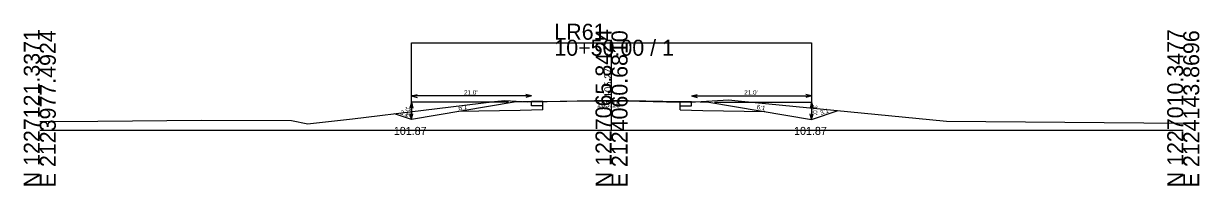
# Model space of a CAD drawing. Extents: x 2126751 to 2128979, y 1225108 to 1234639.
# Drawn here: x 2127773.8 to 2127979.4, y 1225607.5 to 1225635.9 of the extents above; entities that cross this region are included whole.
import ezdxf

# ---------------------------------------------------------------- set-up
doc = ezdxf.new("R2010")
doc.units = 0
for name, color, linetype in [('XS_CELL', 7, 'Continuous'), ('XS_M_DITCH', 7, 'Continuous'), ('XS_P_FINISHED_GRADE', 7, 'Continuous'), ('XS_P_FINISHED_GRADE_ELEV_TX', 7, 'Continuous'), ('XS_P_SUBGRADE_GRANULAR', 7, 'Continuous'), ('XS_P_SUBGRADE_LEVELING', 7, 'Continuous'), ('XS_P_SUBGRADE_PAVEMENT', 7, 'Continuous'), ('XS_P_TX_CLEARZONE', 7, 'Continuous'), ('XS_P_TX_DCH', 7, 'Continuous'), ('XS_P_TX_FS_BS', 7, 'Continuous'), ('XS_X_GROUND', 7, 'Continuous'), ('XS_X_GROUND_TX', 7, 'Continuous')]:
    doc.layers.add(name, color=color, linetype=linetype)

msp = doc.modelspace()

# ---------------------------------------------------------------- linework, layer by layer
at = {"layer": 'XS_CELL'}
for p, q in [((2127876.61, 1225617.21), (2127876.61, 1225633.04)), ((2127776.61, 1225617.21), (2127876.61, 1225617.21)), ((2127876.61, 1225617.21), (2127976.61, 1225617.21))]:
    msp.add_line(p, q, dxfattribs=at)
at = {"layer": 'XS_M_DITCH'}
for p, q in [((2127841.61, 1225619.08), (2127841.61, 1225632.48)), ((2127841.61, 1225632.48), (2127911.61, 1225632.48)), ((2127911.61, 1225632.48), (2127911.61, 1225619.08))]:
    msp.add_line(p, q, dxfattribs=at)
at = {"layer": 'XS_P_FINISHED_GRADE'}
for p, q in [((2127859.61, 1225622.08), (2127841.61, 1225619.08)), ((2127862.61, 1225622.2), (2127859.61, 1225622.08)), ((2127864.61, 1225622.24), (2127862.61, 1225622.2)), ((2127864.61, 1225622.24), (2127876.61, 1225622.48)), ((2127876.61, 1225622.48), (2127888.61, 1225622.24)), ((2127888.61, 1225622.24), (2127890.61, 1225622.2)), ((2127890.61, 1225622.2), (2127893.61, 1225622.08)), ((2127893.61, 1225622.08), (2127911.61, 1225619.08)), ((2127841.61, 1225619.08), (2127838.66, 1225620.07)), ((2127911.61, 1225619.08), (2127916.26, 1225620.63))]:
    msp.add_line(p, q, dxfattribs=at)
at = {"layer": 'XS_P_SUBGRADE_GRANULAR'}
for p, q in [((2127864.61, 1225620.74), (2127864.61, 1225621.49)), ((2127888.61, 1225620.74), (2127888.61, 1225621.49)), ((2127860.61, 1225620.66), (2127849.79, 1225620.45)), ((2127862.61, 1225620.7), (2127860.61, 1225620.66)), ((2127864.61, 1225620.74), (2127862.61, 1225620.7)), ((2127888.61, 1225620.74), (2127890.61, 1225620.7)), ((2127890.61, 1225620.7), (2127892.61, 1225620.66)), ((2127892.61, 1225620.66), (2127903.43, 1225620.45))]:
    msp.add_line(p, q, dxfattribs=at)
at = {"layer": 'XS_P_SUBGRADE_LEVELING'}
for p, q in [((2127864.61, 1225622.2), (2127868.79, 1225622.27)), ((2127864.61, 1225622.24), (2127864.61, 1225622.2)), ((2127868.79, 1225622.27), (2127876.28, 1225622.36)), ((2127876.28, 1225622.36), (2127876.61, 1225622.36)), ((2127876.61, 1225622.36), (2127881.51, 1225622.27)), ((2127881.51, 1225622.27), (2127888.61, 1225622.13)), ((2127888.61, 1225622.24), (2127888.61, 1225622.13))]:
    msp.add_line(p, q, dxfattribs=at)
at = {"layer": 'XS_P_SUBGRADE_PAVEMENT'}
for p, q in [((2127862.61, 1225621.45), (2127862.61, 1225622.2)), ((2127864.61, 1225621.49), (2127862.61, 1225621.45)), ((2127864.61, 1225621.49), (2127864.61, 1225622.2)), ((2127888.61, 1225621.49), (2127888.61, 1225622.13)), ((2127888.61, 1225621.49), (2127890.61, 1225621.45)), ((2127890.61, 1225621.45), (2127890.61, 1225622.2))]:
    msp.add_line(p, q, dxfattribs=at)
at = {"layer": 'XS_P_TX_CLEARZONE'}
for p, q in [((2127841.61, 1225623.2), (2127842.61, 1225623.45)), ((2127841.61, 1225623.2), (2127842.61, 1225622.95)), ((2127862.61, 1225623.2), (2127841.61, 1225623.2)), ((2127862.61, 1225623.2), (2127861.61, 1225623.45)), ((2127862.61, 1225623.2), (2127861.61, 1225622.95)), ((2127890.61, 1225623.2), (2127891.61, 1225623.45)), ((2127890.61, 1225623.2), (2127891.61, 1225622.95)), ((2127890.61, 1225623.2), (2127911.61, 1225623.2)), ((2127911.61, 1225623.2), (2127910.61, 1225623.45)), ((2127911.61, 1225623.2), (2127910.61, 1225622.95)), ((2127841.61, 1225622.08), (2127841.36, 1225621.08)), ((2127841.61, 1225622.08), (2127841.86, 1225621.08)), ((2127841.61, 1225622.08), (2127841.61, 1225619.08)), ((2127858.61, 1225622.08), (2127841.61, 1225622.08)), ((2127894.61, 1225622.08), (2127911.61, 1225622.08)), ((2127911.61, 1225622.08), (2127911.36, 1225621.08)), ((2127911.61, 1225622.08), (2127911.61, 1225619.08)), ((2127911.61, 1225622.08), (2127911.86, 1225621.08)), ((2127841.61, 1225619.08), (2127841.36, 1225620.08)), ((2127841.61, 1225619.08), (2127841.86, 1225620.08)), ((2127911.61, 1225619.08), (2127911.36, 1225620.08)), ((2127911.61, 1225619.08), (2127911.86, 1225620.08))]:
    msp.add_line(p, q, dxfattribs=at)
at = {"layer": 'XS_X_GROUND'}
for p, q in [((2127831.32, 1225619.17), (2127856.14, 1225622.21)), ((2127856.14, 1225622.21), (2127857.94, 1225622.42)), ((2127857.94, 1225622.42), (2127861.96, 1225622.17)), ((2127861.96, 1225622.17), (2127868.79, 1225622.27)), ((2127868.79, 1225622.27), (2127876.28, 1225622.36)), ((2127876.28, 1225622.36), (2127876.61, 1225622.36)), ((2127876.61, 1225622.36), (2127881.51, 1225622.27)), ((2127881.51, 1225622.27), (2127890.39, 1225622.09)), ((2127890.39, 1225622.09), (2127897.1, 1225622.49)), ((2127897.1, 1225622.49), (2127898.74, 1225622.33)), ((2127898.74, 1225622.33), (2127935.21, 1225618.8)), ((2127786.76, 1225618.78), (2127804.87, 1225618.93)), ((2127804.87, 1225618.93), (2127820.63, 1225618.87)), ((2127823.95, 1225618.36), (2127831.32, 1225619.17)), ((2127776.61, 1225618.7), (2127786.76, 1225618.78)), ((2127820.63, 1225618.87), (2127823.48, 1225618.29)), ((2127823.48, 1225618.29), (2127823.95, 1225618.36)), ((2127935.21, 1225618.8), (2127976.61, 1225618.42))]:
    msp.add_line(p, q, dxfattribs=at)

# ---------------------------------------------------------------- texts
at = {"layer": 'XS_CELL'}
for s, p in [('LR61', (2127866.61, 1225633.04)), ('10+50.00 / 1', (2127866.61, 1225630.24))]:
    msp.add_text(s, height=2.8, dxfattribs=at).set_placement(p)
for s, p in [('N 1227121.3371', (2127776.61, 1225607.21)), ('E 2123977.4924', (2127779.41, 1225607.21)), ('N 1227065.8424', (2127876.61, 1225607.21)), ('E 2124060.6810', (2127879.41, 1225607.21)), ('N 1227010.3477', (2127976.61, 1225607.21)), ('E 2124143.8696', (2127979.41, 1225607.21))]:
    msp.add_text(s, height=2.8, rotation=90, dxfattribs=at).set_placement(p)
at = {"layer": 'XS_P_FINISHED_GRADE_ELEV_TX'}
msp.add_text(' 105.27', height=1.25, rotation=90, dxfattribs=at).set_placement((2127876.61, 1225622.48))
at = {"layer": 'XS_P_TX_CLEARZONE'}
for p in [(2127850.82, 1225623.4), (2127899.82, 1225623.4)]:
    msp.add_text("21.0'", height=0.8, dxfattribs=at).set_placement(p)
for rotation, p in [(90, (2127841.41, 1225619.56)), (270, (2127911.81, 1225621.61))]:
    msp.add_text("3.0'", height=0.8, rotation=rotation, dxfattribs=at).set_placement(p)
at = {"layer": 'XS_P_TX_DCH'}
for p in [(2127838.54, 1225616.38), (2127908.54, 1225616.38)]:
    msp.add_text('101.87', height=1.4, dxfattribs=at).set_placement(p)
at = {"layer": 'XS_P_TX_FS_BS'}
for s, rotation, p in [('6:1', 9.4623, (2127849.89, 1225620.67)), ('6:1', 350.5377, (2127901.95, 1225620.9)), ('3:1', 18.4349, (2127913.23, 1225619.83)), ('3:1', 341.5651, (2127839.55, 1225619.98))]:
    msp.add_text(s, height=0.8, rotation=rotation, dxfattribs=at).set_placement(p)
at = {"layer": 'XS_X_GROUND_TX'}
msp.add_text('105.15', height=1, dxfattribs=at).set_placement((2127874.05, 1225621.2))

doc.saveas('drawing.dxf')
